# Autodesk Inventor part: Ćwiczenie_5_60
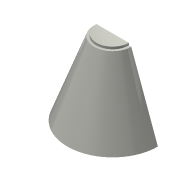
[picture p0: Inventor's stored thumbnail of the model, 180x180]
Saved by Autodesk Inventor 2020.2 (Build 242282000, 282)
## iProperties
Created: 2005-06
Part Number: Ćwiczenie_5_60
Document SubType Name: Modeling
Designer: F.Stasiak
Manufacturer: Standard
Standards Organization: Custom
Density: 1 g/cm^3
Material: Ogólny
Appearance: Gładkie — w kolorze kości słoniowej
Manager: www.cadconsulting.pl
Company: Fabian Stasiak CAD Consulting
Author: F.Stasiak
Subject: Zbiór ćwiczeń. Autodesk Inventor 2020. Kurs podstawowy
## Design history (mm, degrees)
sketch "Szkic1"
  geometry: L1 (-60, 0)-(60, 0); A1 r 60 centre (0, 0) between (-60, 0) and (60, 0); 2 further points
  constraints: 2 end point, 2 midpoint, 2 point on circle, 1 centre point, 1 coincident, 1 horizontal
  dimensions: "d0" = 120 distance of L1.start L1.end
extrude "Wyciągnięcie proste1" new body sketch "Szkic1" distance "d1" = 100; taper "d2" = 0 deg
feature "Szkic powierzchni1" dims angle "d3" = 20 deg
sketch "Szkic2"
  geometry: L1 (-23.603, 100)-(23.603, 100) reference; L2 (-60, 0)-(-23.603, 100) reference; L3 (-23.603, 100)-(-21.603, 100); L4 (-21.603, 100)-(-21.603, 97); L5 (-21.603, 97)-(-24.695, 97); L6 (-23.603, 100)-(-24.695, 97); L7 (0, -10)-(0, 130) reference
  constraints: 8 end point, 2 perpendicular, 2 point on line, 1 collinear
  dimensions: "d4" = 3 distance of L3.end L4.end; "d5" = 2 distance of L1.start L3.end
revolve "Obrót1" sketch "Szkic2" stored, may be unused: angle "d6" = 90 deg
node "Płaszczyzna konstrukcyjna1"
feature "Skorupa1" dims "d8" = 1
node "Bryła1"
node "Korpusy bryłowe"
node "Korpusy powierzchniowe"
